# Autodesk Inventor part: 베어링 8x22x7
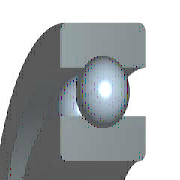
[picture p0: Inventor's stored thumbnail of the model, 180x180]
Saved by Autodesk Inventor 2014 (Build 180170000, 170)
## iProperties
IsCustomPart: 1
Created: 2012-02
Part Number: 베어링 8x22x7
Material: 강철, 연강
Description: 깊은 그루브 볼 베어링
Document SubType Name: Modeling
Standard: KS B 2023
Designer: mduedu
Standards Organization: KS
Language: ko-KR
Size Designation: 608 - 8 x 22 x 7
Categories: <MemberInstance><Categories><Category DisplayName="샤프트 부품" InternalName="7f7aeb1f-a693-4053-b835-cee3144e0d98" Mnemonic="SHFT"><Category DisplayName="베어링" Inter
Density: 7.86 g/cm^3
Appearance: 노란색
Mass: 10.9696 g
Surface Area: 20.0754 cm^2
Volume: 1.39562 cm^3
Author: mduedu
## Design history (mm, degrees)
sketch "스케치" dims "d0" = 3.64 (= -0.26 x WD + 0.26 x BD)
  geometry: L1 (1.68, 7.5)-(5.32, 7.5); L2 (3.5, 7.5)-(3.5, 5.68); L3 (3.5, 7.5)-(3.5, 9.32); L4 (2.148, 6.282)-(0, 6.282); L5 (0, 4)-(7, 4); L6 (2.148, 8.718)-(0, 8.718); L7 (0, 11)-(7, 11); L8 (7, 4)-(7, 6.282); L9 (4.852, 6.282)-(7, 6.282); L10 (4.852, 8.718)-(7, 8.718); L11 (7, 11)-(7, 8.718); L12 (-1.4, 0)-(8.4, 0) reference; L13 (0, -0.3)-(0, 5.3) reference
  constraints: 22 end point, 4 point on line, 2 collinear, 2 perpendicular, 2 symmetric about line, 1 midpoint, 1 parallel, 14 other
  dimensions: "d9" = 8 diameter of L5 L12 (= WD); "d11" = 22 diameter of L7 L12 (= BD); "d12" = 7 distance between parallel lines of L8 L13 (= KB); "d13" = 12.564 diameter of L9 L12 (= 0.326 x BD + 0.674 x WD)
revolve "본체" stored, may be unused: angle "d6" = 90 deg
revolve "볼" stored, may be unused: angle "d7" = 90 deg
pattern_circular "IDS_ARRAYBALL[SIMPL:T]" dims angle "d3" = 360 deg
body "Solid1"
fillet "모깎기1" dims "d1" = 0.3 (= KRS)
other parameters: "WD" = 8 [user parameter; used in 5 equation terms], "BD" = 22 [user parameter; used in 5 equation terms], "KB" = 7 [user parameter; used in 1 equation term], "KRS" = 0.3 [user parameter; used in 1 equation term], "d4" = 0, "d5" = 0, "d8" = 0, "d14" = 0, "d15" = 0, "BBA" = 0 [user parameter], "BC0" = 1370000 [user parameter], "BC" = 3250000 [user parameter], "BR" = 11 (= 0.5 x BD) [user parameter], "WR" = 4 (= 0.5 x WD) [user parameter]
